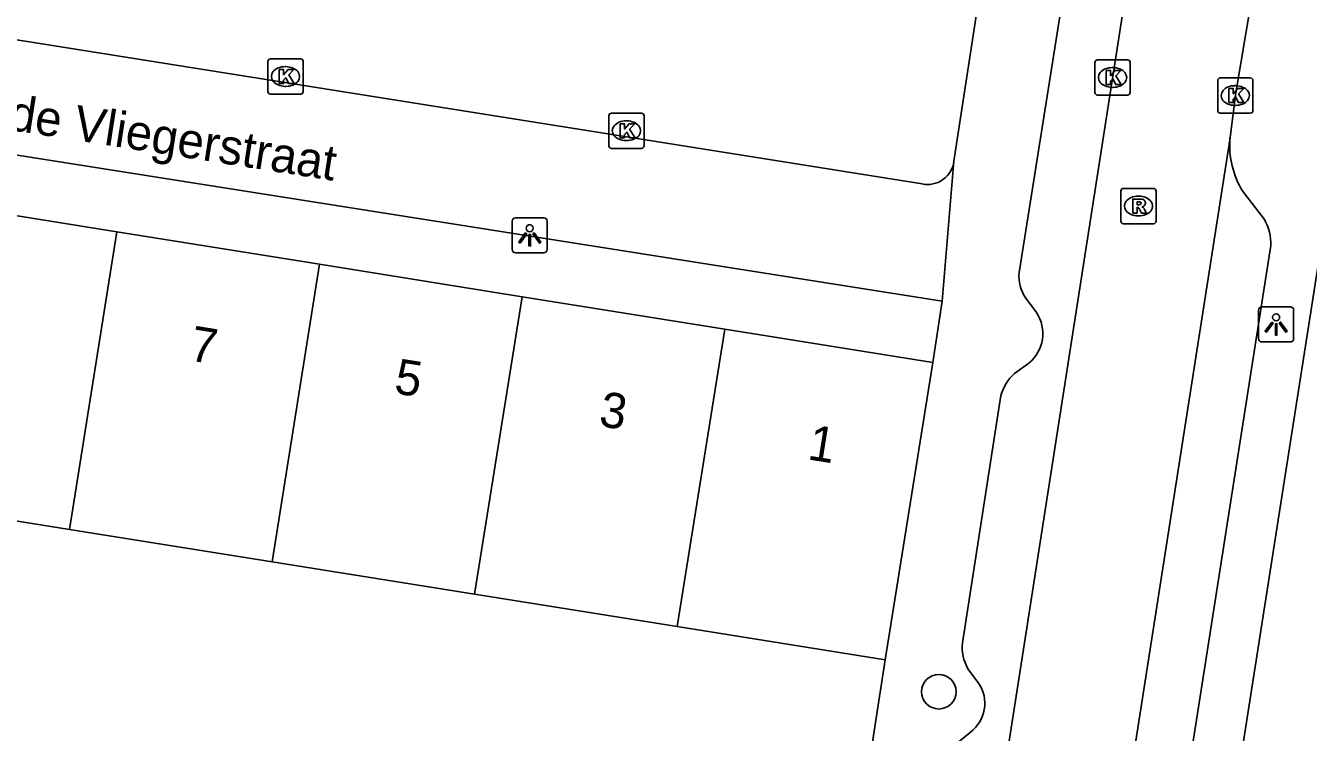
# Model space of a CAD drawing. Extents: x 163010 to 163853, y 382793 to 383982.
# Drawn here: x 163247.59 to 163284, y 383160.96 to 383181.02 of the extents above; entities that cross this region are included whole.
import ezdxf

# ---------------------------------------------------------------- set-up
doc = ezdxf.new("R2010")
doc.units = 0
for name, color, linetype in [('IMGEO_Boom', 7, 'Continuous'), ('IMGEO_Kolk', 7, 'Continuous'), ('IMGEO_Lichtpunt', 7, 'Continuous'), ('IMGEO_Muur', 7, 'Continuous'), ('IMGEO_Openbare_ruimte_label', 7, 'Continuous'), ('IMGEO_Pand', 7, 'Continuous'), ('IMGEO_Pand_nummerreeks', 7, 'Continuous'), ('IMGEO_Rijbaan_lokaal_open', 7, 'Continuous'), ('IMGEO_Rioolput', 7, 'Continuous'), ('IMGEO_Voetpad_open', 7, 'Continuous')]:
    doc.layers.add(name, color=color, linetype=linetype)

msp = doc.modelspace()

# ---------------------------------------------------------------- linework, layer by layer
at = {"layer": 'IMGEO_Boom'}
msp.add_circle((163273.512, 383162.108), 0.489, dxfattribs=at)
at = {"layer": 'IMGEO_Kolk'}
for p, q in [((163254.465, 383179.153), (163254.465, 383180.005)), ((163254.54, 383180.079), (163255.392, 383180.079)), ((163254.953, 383179.859), (163254.978, 383179.859)), ((163255.466, 383180.005), (163255.466, 383179.153)), ((163277.943, 383179.125), (163277.943, 383179.977)), ((163278.018, 383180.051), (163278.87, 383180.051)), ((163278.431, 383179.831), (163278.456, 383179.831)), ((163278.944, 383179.977), (163278.944, 383179.125)), ((163281.428, 383178.613), (163281.428, 383179.465)), ((163281.503, 383179.539), (163282.355, 383179.539)), ((163282.429, 383179.465), (163282.429, 383178.613)), ((163254.976, 383179.299), (163254.951, 383179.299)), ((163278.454, 383179.271), (163278.429, 383179.271)), ((163281.916, 383179.319), (163281.941, 383179.319)), ((163255.392, 383179.079), (163254.54, 383179.079)), ((163278.87, 383179.051), (163278.018, 383179.051)), ((163281.939, 383178.759), (163281.914, 383178.759)), ((163264.143, 383177.613), (163264.143, 383178.465)), ((163264.218, 383178.539), (163265.07, 383178.539)), ((163265.144, 383178.465), (163265.144, 383177.613)), ((163282.355, 383178.539), (163281.503, 383178.539)), ((163264.631, 383178.319), (163264.656, 383178.319)), ((163264.654, 383177.759), (163264.629, 383177.759)), ((163265.07, 383177.539), (163264.218, 383177.539))]:
    msp.add_line(p, q, dxfattribs=at)
for points in [[(163254.465, 383179.153), (163254.465, 383180.005)], [(163254.54, 383180.079), (163255.392, 383180.079)], [(163255.466, 383180.005), (163255.466, 383179.153)], [(163277.943, 383179.125), (163277.943, 383179.977)], [(163278.018, 383180.051), (163278.87, 383180.051)], [(163278.944, 383179.977), (163278.944, 383179.125)], [(163254.786, 383179.779), (163254.909, 383179.779), (163254.909, 383179.628), (163255.039, 383179.779), (163255.203, 383179.779), (163255.057, 383179.628), (163255.21, 383179.379), (163255.058, 383179.379), (163254.973, 383179.543), (163254.909, 383179.476), (163254.909, 383179.379), (163254.786, 383179.379), (163254.786, 383179.779)], [(163278.264, 383179.751), (163278.387, 383179.751), (163278.387, 383179.6), (163278.517, 383179.751), (163278.681, 383179.751), (163278.535, 383179.6), (163278.688, 383179.351), (163278.536, 383179.351), (163278.451, 383179.515), (163278.387, 383179.448), (163278.387, 383179.351), (163278.264, 383179.351), (163278.264, 383179.751)], [(163281.428, 383178.613), (163281.428, 383179.465)], [(163281.503, 383179.539), (163282.355, 383179.539)], [(163282.429, 383179.465), (163282.429, 383178.613)], [(163281.749, 383179.239), (163281.872, 383179.239), (163281.872, 383179.088), (163282.002, 383179.239), (163282.166, 383179.239), (163282.02, 383179.088), (163282.173, 383178.839), (163282.021, 383178.839), (163281.936, 383179.003), (163281.872, 383178.936), (163281.872, 383178.839), (163281.749, 383178.839), (163281.749, 383179.239)], [(163255.392, 383179.079), (163254.54, 383179.079)], [(163278.87, 383179.051), (163278.018, 383179.051)], [(163264.143, 383177.613), (163264.143, 383178.465)], [(163264.218, 383178.539), (163265.07, 383178.539)], [(163265.144, 383178.465), (163265.144, 383177.613)], [(163282.355, 383178.539), (163281.503, 383178.539)], [(163264.464, 383178.239), (163264.587, 383178.239), (163264.587, 383178.088), (163264.717, 383178.239), (163264.881, 383178.239), (163264.735, 383178.088), (163264.888, 383177.839), (163264.736, 383177.839), (163264.651, 383178.003), (163264.587, 383177.936), (163264.587, 383177.839), (163264.464, 383177.839), (163264.464, 383178.239)], [(163265.07, 383177.539), (163264.218, 383177.539)]]:
    msp.add_lwpolyline(points, dxfattribs=at)
for centre, start, end in [((163254.542, 383180.003), 91.552, 178.448), ((163254.542, 383180.003), 91.552, 178.448), ((163255.39, 383180.003), 1.552, 88.448), ((163255.39, 383180.003), 1.552, 88.448), ((163278.02, 383179.975), 91.552, 178.448), ((163278.02, 383179.975), 91.552, 178.448), ((163278.868, 383179.975), 1.552, 88.448), ((163278.868, 383179.975), 1.552, 88.448), ((163281.505, 383179.463), 91.552, 178.448), ((163281.505, 383179.463), 91.552, 178.448), ((163282.353, 383179.463), 1.552, 88.448), ((163282.353, 383179.463), 1.552, 88.448), ((163254.542, 383179.155), 181.552, 268.448), ((163254.542, 383179.155), 181.552, 268.448), ((163255.39, 383179.155), 271.552, 358.448), ((163255.39, 383179.155), 271.552, 358.448), ((163278.02, 383179.127), 181.552, 268.448), ((163278.02, 383179.127), 181.552, 268.448), ((163278.868, 383179.127), 271.552, 358.448), ((163278.868, 383179.127), 271.552, 358.448), ((163264.22, 383178.463), 91.552, 178.448), ((163264.22, 383178.463), 91.552, 178.448), ((163265.068, 383178.463), 1.552, 88.448), ((163265.068, 383178.463), 1.552, 88.448), ((163281.505, 383178.615), 181.552, 268.448), ((163281.505, 383178.615), 181.552, 268.448), ((163282.353, 383178.615), 271.552, 358.448), ((163282.353, 383178.615), 271.552, 358.448), ((163264.22, 383177.615), 181.552, 268.448), ((163264.22, 383177.615), 181.552, 268.448), ((163265.068, 383177.615), 271.552, 358.448), ((163265.068, 383177.615), 271.552, 358.448)]:
    msp.add_arc(centre, 0.0765, start, end, dxfattribs=at)
for centre, major_axis, ratio, start_param, end_param in [((163254.952, 383179.579), (-0.387, 0.002), 0.722429, 4.712389, 7.853982), ((163254.977, 383179.579), (-0.39, 0.002), 0.717154, 1.570796, 4.712389), ((163278.43, 383179.551), (-0.387, 0.002), 0.722429, 4.712389, 7.853982), ((163278.455, 383179.551), (-0.39, 0.002), 0.717154, 1.570796, 4.712389), ((163281.915, 383179.039), (-0.387, 0.002), 0.722429, 4.712389, 7.853982), ((163281.94, 383179.039), (-0.39, 0.002), 0.717154, 1.570796, 4.712389), ((163264.63, 383178.039), (-0.387, 0.002), 0.722429, 4.712389, 7.853982), ((163264.655, 383178.039), (-0.39, 0.002), 0.717154, 1.570796, 4.712389)]:
    msp.add_ellipse(centre, major_axis=major_axis, ratio=ratio, start_param=start_param, end_param=end_param, dxfattribs=at)
at = {"layer": 'IMGEO_Lichtpunt'}
for p, q in [((163261.399, 383175.473), (163261.399, 383174.666)), ((163261.399, 383175.473), (163261.399, 383174.666)), ((163262.301, 383175.568), (163261.493, 383175.568)), ((163262.301, 383175.568), (163261.493, 383175.568)), ((163262.395, 383174.666), (163262.395, 383175.473)), ((163262.395, 383174.666), (163262.395, 383175.473)), ((163261.493, 383174.572), (163262.301, 383174.572)), ((163261.493, 383174.572), (163262.301, 383174.572)), ((163282.589, 383172.943), (163282.589, 383172.136)), ((163282.589, 383172.943), (163282.589, 383172.136)), ((163283.491, 383173.038), (163282.683, 383173.038)), ((163283.491, 383173.038), (163282.683, 383173.038)), ((163283.585, 383172.136), (163283.585, 383172.943)), ((163283.585, 383172.136), (163283.585, 383172.943)), ((163282.683, 383172.042), (163283.491, 383172.042)), ((163282.683, 383172.042), (163283.491, 383172.042))]:
    msp.add_line(p, q, dxfattribs=at)
for points in [[(163261.773, 383175.137), (163261.812, 383175.109), (163261.624, 383174.847), (163261.586, 383174.874), (163261.773, 383175.137)], [(163261.985, 383175.109), (163262.023, 383175.136), (163262.21, 383174.874), (163262.171, 383174.846), (163261.985, 383175.109)], [(163261.875, 383175.089), (163261.922, 383175.089), (163261.922, 383174.767), (163261.875, 383174.767), (163261.875, 383175.089)], [(163282.963, 383172.607), (163283.002, 383172.579), (163282.814, 383172.317), (163282.776, 383172.344), (163282.963, 383172.607)], [(163283.065, 383172.559), (163283.112, 383172.559), (163283.112, 383172.237), (163283.065, 383172.237), (163283.065, 383172.559)], [(163283.175, 383172.579), (163283.213, 383172.606), (163283.4, 383172.344), (163283.361, 383172.316), (163283.175, 383172.579)]]:
    msp.add_lwpolyline(points, dxfattribs=at)
for centre in [(163261.898, 383175.271), (163283.088, 383172.741)]:
    msp.add_circle(centre, 0.0994, dxfattribs=at)
for centre, start, end in [((163261.493, 383175.473), 90, 180), ((163261.493, 383175.473), 90, 180), ((163262.301, 383175.473), 0, 90), ((163262.301, 383175.473), 0, 90), ((163261.493, 383174.666), 180, 270), ((163261.493, 383174.666), 180, 270), ((163262.301, 383174.666), 270, 0), ((163262.301, 383174.666), 270, 360), ((163282.683, 383172.943), 90, 180), ((163282.683, 383172.943), 90, 180), ((163283.491, 383172.943), 0, 90), ((163283.491, 383172.943), 0, 90), ((163282.683, 383172.136), 180, 270), ((163282.683, 383172.136), 180, 270), ((163283.491, 383172.136), 270, 0), ((163283.491, 383172.136), 270, 360)]:
    msp.add_arc(centre, 0.0946, start, end, dxfattribs=at)
at = {"layer": 'IMGEO_Muur'}
msp.add_lwpolyline([(163271.991, 383163.012), (163270.324, 383152.219)], dxfattribs=at)
at = {"layer": 'IMGEO_Pand'}
for points in [[(163248.829, 383166.718), (163242.926, 383167.662), (163243.899, 383173.74), (163244.278, 383176.111), (163250.181, 383175.167)], [(163248.829, 383166.718), (163250.181, 383175.167)], [(163250.181, 383175.167), (163255.934, 383174.246)], [(163254.582, 383165.797), (163255.934, 383174.246)], [(163255.934, 383174.246), (163261.686, 383173.326)], [(163261.686, 383173.326), (163260.334, 383164.877)], [(163261.686, 383173.326), (163267.439, 383172.405)], [(163266.087, 383163.957), (163267.439, 383172.405)], [(163267.439, 383172.405), (163273.342, 383171.461)], [(163273.342, 383171.461), (163271.991, 383163.012)], [(163254.582, 383165.797), (163248.829, 383166.718)], [(163260.334, 383164.877), (163254.582, 383165.797)], [(163266.087, 383163.957), (163260.334, 383164.877)], [(163271.991, 383163.012), (163266.087, 383163.957)]]:
    msp.add_lwpolyline(points, dxfattribs=at)
at = {"layer": 'IMGEO_Rijbaan_lokaal_open'}
for points in [[(163271.253, 383133.395), (163280.323, 383191.611)], [(163281.778, 383177.835), (163281.931, 383179.059), (163282.521, 383182.549)], [(163281.778, 383177.835), (163274.739, 383132.832)]]:
    msp.add_lwpolyline(points, dxfattribs=at)
at = {"layer": 'IMGEO_Rioolput'}
for p, q in [((163278.679, 383175.474), (163278.679, 383176.326)), ((163278.754, 383176.4), (163279.606, 383176.4)), ((163279.68, 383176.326), (163279.68, 383175.474)), ((163279.167, 383176.18), (163279.192, 383176.18)), ((163279.19, 383175.62), (163279.165, 383175.62)), ((163279.606, 383175.4), (163278.754, 383175.4))]:
    msp.add_line(p, q, dxfattribs=at)
for points in [[(163278.679, 383175.474), (163278.679, 383176.326)], [(163278.754, 383176.4), (163279.606, 383176.4)], [(163279.68, 383176.326), (163279.68, 383175.474)], [(163279.268, 383176.098), (163279.016, 383176.1), (163279.016, 383175.7)], [(163279.016, 383175.7), (163279.14, 383175.7), (163279.14, 383175.862), (163279.151, 383175.862)], [(163279.194, 383176.019), (163279.14, 383176.019), (163279.14, 383175.938)], [(163279.14, 383175.938), (163279.192, 383175.938)], [(163279.198, 383175.833), (163279.269, 383175.7), (163279.409, 383175.7), (163279.344, 383175.826)], [(163279.606, 383175.4), (163278.754, 383175.4)]]:
    msp.add_lwpolyline(points, dxfattribs=at)
for centre, radius, start, end in [((163278.756, 383176.324), 0.0765, 91.552, 178.448), ((163278.756, 383176.324), 0.0765, 91.552, 178.448), ((163279.604, 383176.324), 0.0765, 1.552, 88.448), ((163279.604, 383176.324), 0.0765, 1.552, 88.448), ((163279.15, 383175.809), 0.0533, 26.0293, 88.6989), ((163279.176, 383176.127), 0.19, 274.7715, 282.9687), ((163279.2, 383175.923), 0.0964, 77.0061, 93.1865), ((163279.214, 383175.98), 0.0378, 276.6634, 79.6772), ((163279.267, 383175.988), 0.109, 350.3612, 89.416), ((163279.265, 383175.988), 0.112, 277.5842, 350.9817), ((163279.249, 383175.773), 0.108, 29.5134, 73.7905), ((163278.756, 383175.476), 0.0765, 181.552, 268.448), ((163278.756, 383175.476), 0.0765, 181.552, 268.448), ((163279.604, 383175.476), 0.0765, 271.552, 358.448), ((163279.604, 383175.476), 0.0765, 271.552, 358.448)]:
    msp.add_arc(centre, radius, start, end, dxfattribs=at)
for centre, major_axis, ratio, start_param, end_param in [((163279.166, 383175.9), (-0.387, 0.002), 0.722429, 4.712389, 7.853982), ((163279.191, 383175.9), (-0.39, 0.002), 0.717154, 1.570796, 4.712389)]:
    msp.add_ellipse(centre, major_axis=major_axis, ratio=ratio, start_param=start_param, end_param=end_param, dxfattribs=at)
at = {"layer": 'IMGEO_Voetpad_open'}
for points in [[(163275.791, 383174.012), (163278.555, 383191.425), (163278.747, 383191.863)], [(163273.94, 383177.173), (163276.108, 383191.281)], [(163247.162, 383180.646), (163273.036, 383176.528)], [(163273.609, 383173.196), (163244.524, 383177.794), (163244.095, 383177.862)], [(163273.94, 383177.173), (163273.609, 383173.196)], [(163284.671, 383176.706), (163280.237, 383148.453), (163286.065, 383147.534)], [(163282.753, 383175.514), (163282.148, 383176.307)], [(163274.685, 383122.106), (163282.934, 383174.782)], [(163276.28, 383172.879), (163275.98, 383173.284)], [(163273.342, 383171.461), (163273.609, 383173.196)], [(163275.662, 383171.143), (163276.064, 383171.439)], [(163274.18, 383163.502), (163275.275, 383170.517)], [(163270.282, 383151.95), (163270.324, 383152.219), (163271.991, 383163.012)], [(163274.639, 383162.355), (163274.339, 383162.762)], [(163273.997, 383160.619), (163274.398, 383160.956)]]:
    msp.add_lwpolyline(points, dxfattribs=at)
for centre, radius, start, end in [((163284.255, 383177.626), 2.486, 175.175, 212.0489), ((163273.193, 383177.264), 0.753, 257.9786, 353.0367), ((163281.666, 383174.857), 1.27, 356.6239, 31.1538), ((163276.915, 383173.915), 1.128, 175.0846, 214.0225), ((163275.383, 383172.277), 1.08, 309.1035, 33.835), ((163276.454, 383170.221), 1.216, 130.6564, 165.894), ((163275.443, 383163.386), 1.269, 174.7709, 209.4821), ((163273.801, 383161.779), 1.017, 305.9492, 34.5024)]:
    msp.add_arc(centre, radius, start, end, dxfattribs=at)

# ---------------------------------------------------------------- texts
at = {"layer": 'IMGEO_Openbare_ruimte_label'}
msp.add_text('Simon de Vliegerstraat', height=1, rotation=351.084, dxfattribs=at).set_placement((163242.959, 383178.717))
at = {"layer": 'IMGEO_Pand_nummerreeks'}
for s, p in [('7', (163252.207, 383171.52)), ('5', (163258.02, 383170.59)), ('3', (163263.833, 383169.66)), ('1', (163269.758, 383168.712))]:
    msp.add_text(s, height=1, rotation=350.9102, dxfattribs=at).set_placement(p)

doc.saveas('drawing.dxf')
